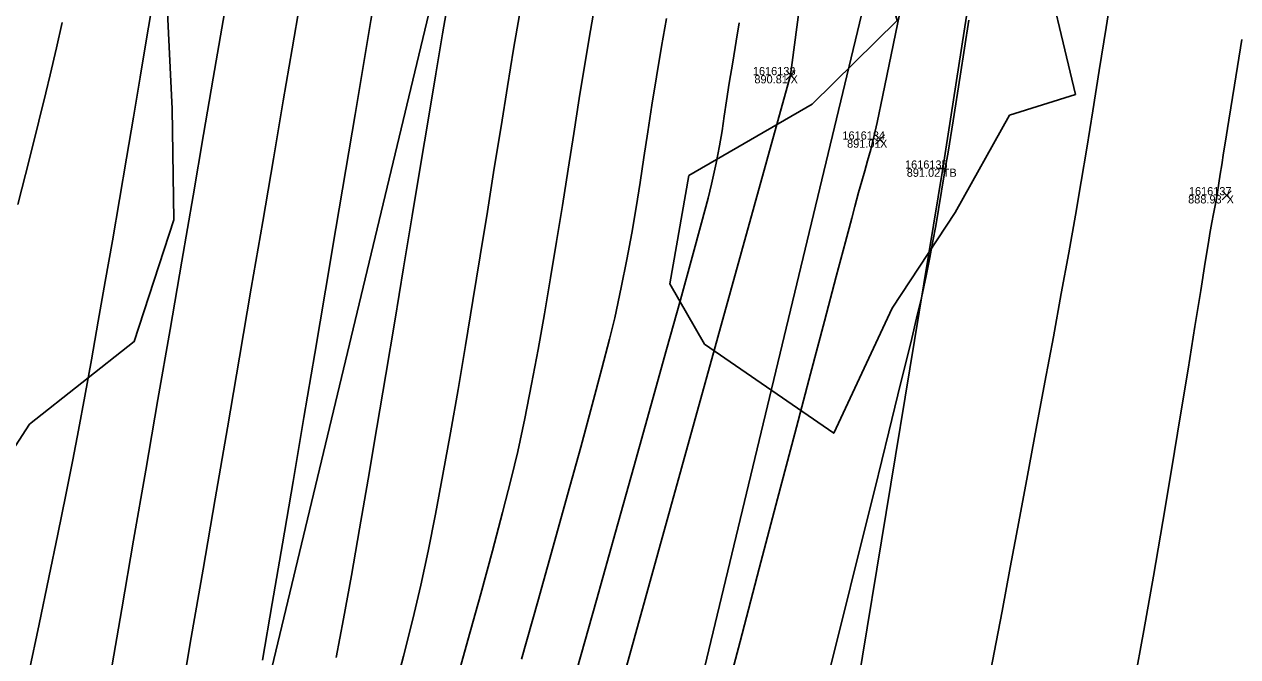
# Model space of a CAD drawing. Extents: x 1957117 to 1971063, y 701601 to 715861.
# Drawn here: x 1963229.1 to 1963281, y 705771 to 705798.1 of the extents above; entities that cross this region are included whole.
import ezdxf

# ---------------------------------------------------------------- set-up
doc = ezdxf.new("R2010")
doc.units = 0
for name, color, linetype in [('AP_X_Lights', 7, 'Continuous'), ('DT_X_Break_Line', 7, 'Continuous'), ('DT_X_Contour_Major', 7, 'Continuous'), ('DT_X_Contour_Minor', 7, 'Continuous'), ('GE_X_CL_20', 7, 'Continuous'), ('HY_X_Water_Edge', 7, 'Continuous'), ('PV_P_Drive', 7, 'Continuous'), ('PV_P_Shoulder', 7, 'Continuous'), ('RS_Raster1', 7, 'Continuous'), ('RW_X_Esmt_RR', 7, 'Continuous'), ('SC_Scratch1', 7, 'Continuous'), ('SC_Shading5', 7, 'Continuous'), ('VG_X_Tree_Line_Rt', 7, 'Continuous')]:
    doc.layers.add(name, color=color, linetype=linetype)

msp = doc.modelspace()

# ---------------------------------------------------------------- linework, layer by layer
at = {"layer": 'AP_X_Lights'}
for p, q in [((1963261.635, 705795.728), (1963262.023, 705796.118)), ((1963261.635, 705796.118), (1963262.023, 705795.728)), ((1963265.461, 705792.975), (1963265.849, 705793.365)), ((1963265.461, 705793.365), (1963265.849, 705792.975)), ((1963280.282, 705790.592), (1963280.67, 705790.982)), ((1963280.282, 705790.982), (1963280.67, 705790.592))]:
    msp.add_line(p, q, dxfattribs=at)
at = {"layer": 'DT_X_Break_Line'}
for points in [[(1963248.355, 705747.376), (1963261.829, 705795.923), (1963267.581, 705840.559), (1963287.153, 705892.264), (1963291.083, 705944.763), (1963301.574, 705996.211), (1963311.528, 706039.027), (1963334.717, 706086.75), (1963331.957, 706106.508), (1963348.786, 706182.796), (1963365.664, 706223.934), (1963373.462, 706281.461), (1963387.853, 706330.217), (1963397.264, 706379.501), (1963407.696, 706427.592), (1963426.755, 706477.16), (1963442.136, 706524.014), (1963446.007, 706569.971), (1963489.391, 706666.839), (1963500.526, 706701.536)], [(1963509.92, 706697.686), (1963502.832, 706666.547), (1963464.625, 706568.104), (1963439.113, 706472.593), (1963428.782, 706425.675), (1963415.739, 706378.185), (1963398.991, 706327.191), (1963392.393, 706279.173), (1963377.9, 706227.719), (1963369.87, 706175.335), (1963345.874, 706098.69), (1963341.112, 706081.071), (1963328.328, 706036.261), (1963311.276, 705989.111), (1963300.503, 705940.076), (1963293.199, 705890.767), (1963276.592, 705844.792), (1963268.336, 705791.927), (1963260.722, 705745.719)]]:
    msp.add_lwpolyline(points, dxfattribs=at)
at = {"layer": 'DT_X_Contour_Major'}
for points in [[(1963248.707, 705826.66), (1963248.246, 705823.969), (1963247.773, 705821.196), (1963247.296, 705818.385), (1963246.822, 705815.581), (1963246.357, 705812.828), (1963245.909, 705810.171), (1963245.484, 705807.652), (1963245.09, 705805.317), (1963244.733, 705803.211), (1963244.42, 705801.376), (1963244.159, 705799.858), (1963243.886, 705798.269), (1963243.565, 705796.38), (1963243.203, 705794.237), (1963242.807, 705791.884), (1963242.384, 705789.366), (1963241.941, 705786.729), (1963241.484, 705784.017), (1963241.021, 705781.275), (1963240.559, 705778.548), (1963240.104, 705775.881), (1963239.664, 705773.319), (1963239.246, 705770.907)], [(1963248.707, 705826.66), (1963248.246, 705823.969), (1963247.773, 705821.196), (1963247.296, 705818.385), (1963246.822, 705815.581), (1963246.357, 705812.828), (1963245.909, 705810.171), (1963245.484, 705807.652), (1963245.09, 705805.317), (1963244.733, 705803.211), (1963244.42, 705801.376), (1963244.159, 705799.858), (1963243.886, 705798.269), (1963243.565, 705796.38), (1963243.203, 705794.237), (1963242.807, 705791.884), (1963242.384, 705789.366), (1963241.941, 705786.729), (1963241.484, 705784.017), (1963241.021, 705781.275), (1963240.559, 705778.548), (1963240.104, 705775.881), (1963239.664, 705773.319), (1963239.246, 705770.907)], [(1963275.62, 705799.89), (1963275.321, 705797.962), (1963275.032, 705796.121), (1963274.757, 705794.392), (1963274.497, 705792.801), (1963274.258, 705791.371), (1963274.009, 705789.935), (1963273.723, 705788.329), (1963273.407, 705786.582), (1963273.067, 705784.726), (1963272.709, 705782.79), (1963272.339, 705780.806), (1963271.965, 705778.804), (1963271.591, 705776.815), (1963271.224, 705774.868), (1963270.871, 705772.995), (1963270.537, 705771.226), (1963270.229, 705769.592)], [(1963275.62, 705799.89), (1963275.321, 705797.962), (1963275.032, 705796.121), (1963274.757, 705794.392), (1963274.497, 705792.801), (1963274.258, 705791.371), (1963274.009, 705789.935), (1963273.723, 705788.329), (1963273.407, 705786.582), (1963273.067, 705784.726), (1963272.709, 705782.79), (1963272.339, 705780.806), (1963271.965, 705778.804), (1963271.591, 705776.815), (1963271.224, 705774.868), (1963270.871, 705772.995), (1963270.537, 705771.226), (1963270.229, 705769.592)], [(1963259.624, 705798.159), (1963259.505, 705797.381), (1963259.355, 705796.474), (1963259.206, 705795.578), (1963259.091, 705794.831), (1963258.994, 705794.174), (1963258.898, 705793.549), (1963258.787, 705792.895), (1963258.644, 705792.154), (1963258.453, 705791.267), (1963258.302, 705790.664), (1963258.02, 705789.607), (1963257.621, 705788.144), (1963257.119, 705786.321), (1963256.526, 705784.187), (1963255.857, 705781.787), (1963255.126, 705779.17), (1963254.345, 705776.382), (1963253.53, 705773.47), (1963252.693, 705770.482)], [(1963259.624, 705798.159), (1963259.505, 705797.381), (1963259.355, 705796.474), (1963259.206, 705795.578), (1963259.091, 705794.831), (1963258.994, 705794.174), (1963258.898, 705793.549), (1963258.787, 705792.895), (1963258.644, 705792.154), (1963258.453, 705791.267), (1963258.302, 705790.664), (1963258.02, 705789.607), (1963257.621, 705788.144), (1963257.119, 705786.321), (1963256.526, 705784.187), (1963255.857, 705781.787), (1963255.126, 705779.17), (1963254.345, 705776.382), (1963253.53, 705773.47), (1963252.693, 705770.482)]]:
    msp.add_lwpolyline(points, dxfattribs=at)
at = {"layer": 'DT_X_Contour_Minor'}
for points in [[(1963245.903, 705828.273), (1963245.338, 705824.995), (1963244.766, 705821.68), (1963244.198, 705818.385), (1963243.643, 705815.165), (1963243.111, 705812.076), (1963242.611, 705809.173), (1963242.152, 705806.512), (1963241.744, 705804.148), (1963241.397, 705802.137), (1963241.12, 705800.535), (1963240.849, 705798.964), (1963240.519, 705797.044), (1963240.137, 705794.822), (1963239.713, 705792.344), (1963239.254, 705789.66), (1963238.767, 705786.816), (1963238.261, 705783.86), (1963237.744, 705780.839), (1963237.223, 705777.801), (1963236.706, 705774.794), (1963236.203, 705771.865), (1963235.719, 705769.062)], [(1963245.903, 705828.273), (1963245.338, 705824.995), (1963244.766, 705821.68), (1963244.198, 705818.385), (1963243.643, 705815.165), (1963243.111, 705812.076), (1963242.611, 705809.173), (1963242.152, 705806.512), (1963241.744, 705804.148), (1963241.397, 705802.137), (1963241.12, 705800.535), (1963240.849, 705798.964), (1963240.519, 705797.044), (1963240.137, 705794.822), (1963239.713, 705792.344), (1963239.254, 705789.66), (1963238.767, 705786.816), (1963238.261, 705783.86), (1963237.744, 705780.839), (1963237.223, 705777.801), (1963236.706, 705774.794), (1963236.203, 705771.865), (1963235.719, 705769.062)], [(1963242.552, 705827.117), (1963242.119, 705824.613), (1963241.669, 705822.011), (1963241.21, 705819.354), (1963240.75, 705816.684), (1963240.295, 705814.044), (1963239.852, 705811.476), (1963239.429, 705809.023), (1963239.033, 705806.727), (1963238.672, 705804.632), (1963238.352, 705802.779), (1963238.081, 705801.212), (1963237.828, 705799.751), (1963237.513, 705797.928), (1963237.144, 705795.789), (1963236.729, 705793.382), (1963236.276, 705790.757), (1963235.794, 705787.961), (1963235.291, 705785.042), (1963234.774, 705782.048), (1963234.253, 705779.028), (1963233.735, 705776.029), (1963233.229, 705773.1), (1963232.743, 705770.289)], [(1963242.552, 705827.117), (1963242.119, 705824.613), (1963241.669, 705822.011), (1963241.21, 705819.354), (1963240.75, 705816.684), (1963240.295, 705814.044), (1963239.852, 705811.476), (1963239.429, 705809.023), (1963239.033, 705806.727), (1963238.672, 705804.632), (1963238.352, 705802.779), (1963238.081, 705801.212), (1963237.828, 705799.751), (1963237.513, 705797.928), (1963237.144, 705795.789), (1963236.729, 705793.382), (1963236.276, 705790.757), (1963235.794, 705787.961), (1963235.291, 705785.042), (1963234.774, 705782.048), (1963234.253, 705779.028), (1963233.735, 705776.029), (1963233.229, 705773.1), (1963232.743, 705770.289)], [(1963234.557, 705799.058), (1963234.291, 705797.485), (1963234.012, 705795.833), (1963233.724, 705794.123), (1963233.428, 705792.374), (1963233.128, 705790.607), (1963232.825, 705788.842), (1963232.524, 705787.098), (1963232.226, 705785.395), (1963231.934, 705783.754), (1963231.65, 705782.195), (1963231.378, 705780.737), (1963231.133, 705779.473), (1963230.835, 705777.979), (1963230.49, 705776.288), (1963230.106, 705774.432), (1963229.693, 705772.446), (1963229.256, 705770.362)], [(1963234.557, 705799.058), (1963234.291, 705797.485), (1963234.012, 705795.833), (1963233.724, 705794.123), (1963233.428, 705792.374), (1963233.128, 705790.607), (1963232.825, 705788.842), (1963232.524, 705787.098), (1963232.226, 705785.395), (1963231.934, 705783.754), (1963231.65, 705782.195), (1963231.378, 705780.737), (1963231.133, 705779.473), (1963230.835, 705777.979), (1963230.49, 705776.288), (1963230.106, 705774.432), (1963229.693, 705772.446), (1963229.256, 705770.362)], [(1963247.198, 705799.181), (1963246.943, 705797.686), (1963246.655, 705795.978), (1963246.341, 705794.09), (1963246.004, 705792.055), (1963245.65, 705789.907), (1963245.282, 705787.68), (1963244.905, 705785.407), (1963244.524, 705783.12), (1963244.143, 705780.855), (1963243.767, 705778.644), (1963243.401, 705776.521), (1963243.048, 705774.518), (1963242.713, 705772.671), (1963242.402, 705771.011)], [(1963247.198, 705799.181), (1963246.943, 705797.686), (1963246.655, 705795.978), (1963246.341, 705794.09), (1963246.004, 705792.055), (1963245.65, 705789.907), (1963245.282, 705787.68), (1963244.905, 705785.407), (1963244.524, 705783.12), (1963244.143, 705780.855), (1963243.767, 705778.644), (1963243.401, 705776.521), (1963243.048, 705774.518), (1963242.713, 705772.671), (1963242.402, 705771.011)], [(1963253.502, 705799.161), (1963253.277, 705797.828), (1963253.035, 705796.4), (1963252.795, 705794.93), (1963252.555, 705793.427), (1963252.313, 705791.9), (1963252.069, 705790.356), (1963251.821, 705788.805), (1963251.567, 705787.255), (1963251.306, 705785.716), (1963251.036, 705784.194), (1963250.756, 705782.7), (1963250.464, 705781.242), (1963250.16, 705779.829), (1963249.88, 705778.651), (1963249.517, 705777.22), (1963249.08, 705775.571), (1963248.582, 705773.737), (1963248.032, 705771.75), (1963247.441, 705769.643)], [(1963253.502, 705799.161), (1963253.277, 705797.828), (1963253.035, 705796.4), (1963252.795, 705794.93), (1963252.555, 705793.427), (1963252.313, 705791.9), (1963252.069, 705790.356), (1963251.821, 705788.805), (1963251.567, 705787.255), (1963251.306, 705785.716), (1963251.036, 705784.194), (1963250.756, 705782.7), (1963250.464, 705781.242), (1963250.16, 705779.829), (1963249.88, 705778.651), (1963249.517, 705777.22), (1963249.08, 705775.571), (1963248.582, 705773.737), (1963248.032, 705771.75), (1963247.441, 705769.643)], [(1963266.594, 705798.999), (1963266.135, 705796.798), (1963265.774, 705795.074), (1963265.526, 705793.9), (1963265.405, 705793.35), (1963265.255, 705792.746), (1963265.124, 705792.257), (1963265.002, 705791.826), (1963264.877, 705791.396), (1963264.738, 705790.909), (1963264.574, 705790.308), (1963264.442, 705789.813), (1963264.172, 705788.794), (1963263.778, 705787.307), (1963263.276, 705785.408), (1963262.68, 705783.153), (1963262.006, 705780.599), (1963261.269, 705777.802), (1963260.485, 705774.819), (1963259.667, 705771.706), (1963258.833, 705768.518)], [(1963266.594, 705798.999), (1963266.135, 705796.798), (1963265.774, 705795.074), (1963265.526, 705793.9), (1963265.405, 705793.35), (1963265.255, 705792.746), (1963265.124, 705792.257), (1963265.002, 705791.826), (1963264.877, 705791.396), (1963264.738, 705790.909), (1963264.574, 705790.308), (1963264.442, 705789.813), (1963264.172, 705788.794), (1963263.778, 705787.307), (1963263.276, 705785.408), (1963262.68, 705783.153), (1963262.006, 705780.599), (1963261.269, 705777.802), (1963260.485, 705774.819), (1963259.667, 705771.706), (1963258.833, 705768.518)], [(1963250.238, 705798.504), (1963249.987, 705797.033), (1963249.723, 705795.434), (1963249.446, 705793.729), (1963249.159, 705791.94), (1963248.862, 705790.088), (1963248.556, 705788.194), (1963248.245, 705786.28), (1963247.929, 705784.367), (1963247.609, 705782.476), (1963247.287, 705780.63), (1963246.965, 705778.848), (1963246.645, 705777.153), (1963246.327, 705775.567), (1963246.013, 705774.11), (1963245.671, 705772.655), (1963245.275, 705771.076), (1963244.832, 705769.394)], [(1963250.238, 705798.504), (1963249.987, 705797.033), (1963249.723, 705795.434), (1963249.446, 705793.729), (1963249.159, 705791.94), (1963248.862, 705790.088), (1963248.556, 705788.194), (1963248.245, 705786.28), (1963247.929, 705784.367), (1963247.609, 705782.476), (1963247.287, 705780.63), (1963246.965, 705778.848), (1963246.645, 705777.153), (1963246.327, 705775.567), (1963246.013, 705774.11), (1963245.671, 705772.655), (1963245.275, 705771.076), (1963244.832, 705769.394)], [(1963230.685, 705798.17), (1963230.439, 705797.094), (1963230.168, 705795.935), (1963229.98, 705795.164), (1963229.678, 705793.951), (1963229.276, 705792.347), (1963228.787, 705790.399)], [(1963230.685, 705798.17), (1963230.439, 705797.094), (1963230.168, 705795.935), (1963229.98, 705795.164), (1963229.678, 705793.951), (1963229.276, 705792.347), (1963228.787, 705790.399)], [(1963256.518, 705798.351), (1963256.316, 705797.151), (1963256.097, 705795.851), (1963255.903, 705794.641), (1963255.727, 705793.499), (1963255.56, 705792.403), (1963255.394, 705791.331), (1963255.221, 705790.26), (1963255.035, 705789.169), (1963254.825, 705788.034), (1963254.585, 705786.835), (1963254.307, 705785.548), (1963254.085, 705784.626), (1963253.761, 705783.37), (1963253.347, 705781.819), (1963252.854, 705780.009), (1963252.294, 705777.978), (1963251.677, 705775.765), (1963251.016, 705773.406), (1963250.321, 705770.94)], [(1963256.518, 705798.351), (1963256.316, 705797.151), (1963256.097, 705795.851), (1963255.903, 705794.641), (1963255.727, 705793.499), (1963255.56, 705792.403), (1963255.394, 705791.331), (1963255.221, 705790.26), (1963255.035, 705789.169), (1963254.825, 705788.034), (1963254.585, 705786.835), (1963254.307, 705785.548), (1963254.085, 705784.626), (1963253.761, 705783.37), (1963253.347, 705781.819), (1963252.854, 705780.009), (1963252.294, 705777.978), (1963251.677, 705775.765), (1963251.016, 705773.406), (1963250.321, 705770.94)], [(1963263.251, 705769.485), (1963264.02, 705772.56), (1963264.75, 705775.491), (1963265.426, 705778.215), (1963266.032, 705780.664), (1963266.551, 705782.774), (1963266.967, 705784.477), (1963267.264, 705785.71), (1963267.426, 705786.405), (1963267.628, 705787.347), (1963267.788, 705788.131), (1963267.919, 705788.822), (1963268.036, 705789.483), (1963268.154, 705790.176), (1963268.286, 705790.967), (1963268.446, 705791.917), (1963268.562, 705792.627), (1963268.776, 705793.973), (1963269.078, 705795.882), (1963269.455, 705798.283)], [(1963263.251, 705769.485), (1963264.02, 705772.56), (1963264.75, 705775.491), (1963265.426, 705778.215), (1963266.032, 705780.664), (1963266.551, 705782.774), (1963266.967, 705784.477), (1963267.264, 705785.71), (1963267.426, 705786.405), (1963267.628, 705787.347), (1963267.788, 705788.131), (1963267.919, 705788.822), (1963268.036, 705789.483), (1963268.154, 705790.176), (1963268.286, 705790.967), (1963268.446, 705791.917), (1963268.562, 705792.627), (1963268.776, 705793.973), (1963269.078, 705795.882), (1963269.455, 705798.283)], [(1963276.53, 705769.915), (1963276.939, 705772.17), (1963277.347, 705774.494), (1963277.748, 705776.832), (1963278.133, 705779.124), (1963278.496, 705781.316), (1963278.828, 705783.349), (1963279.121, 705785.168), (1963279.369, 705786.714), (1963279.563, 705787.932), (1963279.696, 705788.763), (1963279.76, 705789.152), (1963279.847, 705789.623), (1963279.917, 705789.988), (1963279.986, 705790.354), (1963280.069, 705790.825), (1963280.148, 705791.306), (1963280.207, 705791.695), (1963280.266, 705792.093), (1963280.346, 705792.596), (1963280.413, 705793.017), (1963280.571, 705794.005), (1963280.809, 705795.502), (1963281.121, 705797.449)], [(1963276.53, 705769.915), (1963276.939, 705772.17), (1963277.347, 705774.494), (1963277.748, 705776.832), (1963278.133, 705779.124), (1963278.496, 705781.316), (1963278.828, 705783.349), (1963279.121, 705785.168), (1963279.369, 705786.714), (1963279.563, 705787.932), (1963279.696, 705788.763), (1963279.76, 705789.152), (1963279.847, 705789.623), (1963279.917, 705789.988), (1963279.986, 705790.354), (1963280.069, 705790.825), (1963280.148, 705791.306), (1963280.207, 705791.695), (1963280.266, 705792.093), (1963280.346, 705792.596), (1963280.413, 705793.017), (1963280.571, 705794.005), (1963280.809, 705795.502), (1963281.121, 705797.449)]]:
    msp.add_lwpolyline(points, dxfattribs=at)
at = {"layer": 'GE_X_CL_20'}
msp.add_lwpolyline([(1963418.3, 706437.397), (1962895.621, 704261.062)], dxfattribs=at)
at = {"layer": 'HY_X_Water_Edge'}
msp.add_spline([(1963191.723, 701994.048), (1963062.047, 702441.167), (1962863.491, 703169.356), (1962827.53, 703438.691), (1962823.213, 703537.412), (1962817.962, 703593.874), (1962817.97, 703697.316), (1962828.582, 703804.235), (1962836.461, 703844.734), (1962850.687, 703896.004), (1962867.251, 703938.846), (1962873.848, 703992.355), (1962884.135, 704091.371), (1962891.241, 704140.854), (1962897.382, 704180.529), (1962905.467, 704230.979), (1962943.949, 704328.022), (1962948.537, 704378.842), (1962964.114, 704426.264), (1963004.885, 704570.73), (1963042.054, 704716.522), (1963062.038, 704814.417), (1963072.171, 704860.237), (1963090.023, 704956.798), (1963107.066, 705031.783), (1963133.773, 705105.742), (1963148.685, 705206.74), (1963175.48, 705301.059), (1963191.635, 705353.417), (1963210.988, 705447.286), (1963219.532, 705497.27), (1963230.124, 705549.475), (1963251.052, 705591.159), (1963275.289, 705693.429), (1963292.982, 705784.032), (1963302.841, 705839.645), (1963335.126, 705936.766), (1963359.752, 706046.75), (1963389.133, 706177.299), (1963417.827, 706273.456), (1963475.868, 706451.902), (1963533.782, 706640.53), (1963553.86, 706696.984), (1963580.184, 706715.425), (1963609.172, 706718.73), (1963617.062, 706714.691), (1963619.447, 706694.678), (1963564.282, 706533.07), (1963531.853, 706395.229), (1963434.4, 706006.96), (1963354.09, 705679.186), (1963237.513, 705206.07), (1963167.369, 704892.962), (1963059.145, 704434.176), (1962907.914, 703908.742), (1962877.458, 703703.326), (1962898.357, 703412.121), (1962942.65, 703052.267), (1963048.963, 702674.866), (1963191.468, 702189.666), (1963245.396, 702019.832)], degree=3, dxfattribs=at)
at = {"layer": 'PV_P_Drive'}
for p, q in [((1963268.19, 705791.927), (1963268.482, 705791.927)), ((1963268.336, 705792.073), (1963268.336, 705791.781)), ((1963268.336, 705791.927), (1963268.336, 705791.927))]:
    msp.add_line(p, q, dxfattribs=at)
at = {"layer": 'RW_X_Esmt_RR'}
msp.add_lwpolyline([(1962866.45, 704268.068), (1963123.345, 705337.727), (1963135.496, 705336.937), (1963400.797, 706441.601)], dxfattribs=at)
at = {"layer": 'SC_Shading5'}
for points in [[(1963026.912, 704294.121), (1963138.818, 704737.794), (1963251.679, 705213.963), (1963374.306, 705730.111), (1963454.783, 706045.593), (1963517.244, 706296.713), (1963562.763, 706479.256), (1963580.13, 706553.799), (1963589.678, 706586.994)], [(1963609.915, 706579.703), (1963587.283, 706499.153), (1963552.056, 706354.005), (1963480.911, 706069.234), (1963357.401, 705576.869), (1963272.751, 705226.931), (1963210.247, 704956.481), (1963044.97, 704288.881)]]:
    msp.add_spline(points, degree=3, dxfattribs=at)
at = {"layer": 'VG_X_Tree_Line_Rt'}
for points in [[(1963234.818, 705827.01), (1963234.551, 705819.93), (1963234.944, 705814.318), (1963235.74, 705808.247), (1963235.52, 705802.53), (1963235.18, 705798.611), (1963235.385, 705794.481), (1963235.455, 705789.729), (1963233.764, 705784.529), (1963229.289, 705780.991), (1963227.913, 705778.901), (1963225.757, 705777.228), (1963221.29, 705777.054), (1963223.781, 705773.218), (1963226.609, 705770.346)], [(1963283.248, 705807.448), (1963278.543, 705807.149), (1963273.61, 705804.275), (1963272.486, 705801.503), (1963274.011, 705795.098), (1963271.192, 705794.21), (1963268.866, 705790.045), (1963266.171, 705785.959), (1963263.679, 705780.604), (1963258.153, 705784.424), (1963256.668, 705786.994), (1963257.476, 705791.627), (1963262.751, 705794.679), (1963266.389, 705798.263), (1963265.138, 705802.616), (1963262.221, 705805.102), (1963263.66, 705808.395), (1963267.084, 705811.416), (1963272.211, 705814.541), (1963277.999, 705817.361), (1963280, 705813.094), (1963284.097, 705810.616)]]:
    msp.add_lwpolyline(points, dxfattribs=at)

# ---------------------------------------------------------------- texts
at = {"layer": 'PV_P_Shoulder'}
for s, p in [('890.81', (1963260.282, 705795.573)), ('891.01', (1963264.246, 705792.82)), ('891.02', (1963266.798, 705791.577)), ('888.93', (1963278.831, 705790.437))]:
    msp.add_text(s, height=0.35, dxfattribs=at).set_placement(p)
at = {"layer": 'RS_Raster1'}
for s, p in [('1616133', (1963260.217, 705795.923)), ('1616134', (1963264.046, 705793.17)), ('1616135', (1963266.724, 705791.927)), ('1616137', (1963278.864, 705790.787))]:
    msp.add_text(s, height=0.35, dxfattribs=at).set_placement(p)
at = {"layer": 'SC_Scratch1'}
for s, p in [('X', (1963261.829, 705795.573)), ('X', (1963265.655, 705792.82)), ('TB', (1963268.336, 705791.577)), ('X', (1963280.476, 705790.437))]:
    msp.add_text(s, height=0.35, dxfattribs=at).set_placement(p)

doc.saveas('drawing.dxf')
